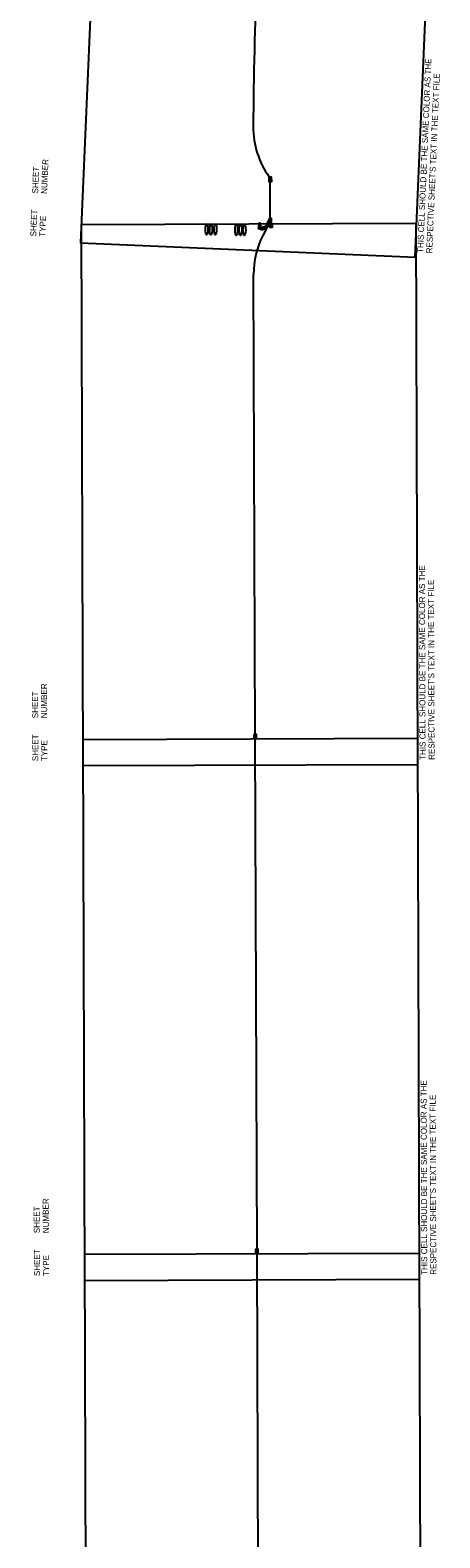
# Model space of a CAD drawing. Extents: x 601462 to 605493, y 331960 to 402715.
# Drawn here: x 602465 to 603657, y 394361 to 398753 of the extents above; entities that cross this region are included whole.
import ezdxf

# ---------------------------------------------------------------- set-up
doc = ezdxf.new("R2010")
doc.units = 0
for name, color, linetype in [('Default', 7, 'Continuous'), ('P_FTMS', 7, 'Continuous'), ('P_FTMSConduit', 7, 'Continuous'), ('P_MISC_TXT_1A (Construction)', 7, 'Continuous'), ('P_MISC_TXT_1B (Construction)', 7, 'Continuous')]:
    doc.layers.add(name, color=color, linetype=linetype)

# ---------------------------------------------------------------- blocks, each defined once
blk = doc.blocks.new('FMD')
at = {"layer": 'P_FTMS'}
for p, q in [((17, 18), (-17, 18)), ((-16, 16), (-16, 18)), ((16, 16), (-16, 16)), ((-15, 15), (-15, 20)), ((15, 19), (-15, 19)), ((15, 15), (-15, 15)), ((14, 20), (-14, 20)), ((13, 22), (-13, 22)), ((-13, 13), (-13, 21)), ((13, 13), (-13, 13)), ((-12, 12), (-12, 23)), ((12, 12), (-12, 12)), ((11, 23), (-11, 23)), ((10, 25), (-10, 25)), ((-10, 10), (-10, 24)), ((10, 10), (-10, 10)), ((-9, 9), (-9, 26)), ((9, 9), (-9, 9)), ((8, 26), (-8, 26)), ((7, 28), (-7, 28)), ((-7, 7), (-7, 27)), ((7, 7), (-7, 7)), ((-6, 6), (-6, 29)), ((6, 6), (-6, 6)), ((5, 29), (-5, 29)), ((4, 31), (-4, 31)), ((-4, 4), (-4, 30)), ((4, 4), (-4, 4)), ((-3, 3), (-3, 32)), ((3, 3), (-3, 3)), ((2, 32), (-2, 32)), ((1, 34), (-1, 34)), ((-1, 1), (-1, 33)), ((1, 1), (-1, 1)), ((0, 0), (0, 34)), ((1, 1), (1, 33)), ((3, 3), (3, 32)), ((4, 4), (4, 30)), ((6, 6), (6, 29)), ((7, 7), (7, 27)), ((9, 9), (9, 26)), ((10, 10), (10, 24)), ((12, 12), (12, 23)), ((13, 13), (13, 21)), ((15, 15), (15, 20)), ((16, 16), (16, 18))]:
    blk.add_line(p, q, dxfattribs=at)
blk.add_lwpolyline([(-17, 17), (0, 34), (17, 17), (0, 0)], close=True, dxfattribs=at)
blk = doc.blocks.new('POINT_DISPLAY')
at = {"layer": 'Default'}
blk.add_line((0, 0), (0, 0), dxfattribs=at)
blk = doc.blocks.new('_U229')
at = {"layer": 'P_FTMS'}
for p, q in [((-5, 3), (2, 0)), ((-2, 3), (-4, 0)), ((-2, 3), (-4, 0)), ((-2, 3), (-4, 1)), ((-3, 3), (-4, 1)), ((-3, 3), (-4, 1)), ((-3, 3), (-4, 2)), ((-4, 3), (-4, 2)), ((-4, 3), (-4, 3)), ((-4, 3), (2, 0)), ((-4, 3), (2, 0)), ((-4, 3), (1, 0)), ((-4, 2), (1, -1)), ((-4, 2), (1, -1)), ((-4, 2), (0, -1)), ((-4, 1), (0, -1)), ((-4, 1), (0, -1)), ((-4, 0), (0, -2)), ((1, 3), (-3, -3)), ((0, 3), (-3, -3)), ((0, 3), (-3, -2)), ((0, 3), (-3, -2)), ((-1, 3), (-3, -2)), ((-1, 3), (-3, -1)), ((-1, 3), (-3, -1)), ((-3, 3), (2, 0)), ((1, 3), (-2, -3)), ((1, 3), (-2, -3)), ((-2, 3), (3, 1)), ((2, 3), (-1, -2)), ((2, 3), (-1, -2)), ((-1, 3), (3, 1)), ((2, 3), (0, -1)), ((0, 3), (3, 1)), ((3, 3), (1, -1)), ((1, 3), (4, 1)), ((1, 3), (3, 1)), ((3, 2), (1, 0)), ((2, 3), (4, 2)), ((3, 2), (2, 0)), ((4, 2), (3, 1)), ((4, 2), (3, 1)), ((3, 2), (4, 2)), ((4, 2), (4, 2)), ((4, 2), (4, 2)), ((-4, 0), (-1, -2)), ((-3, 0), (-1, -2)), ((-3, -1), (-1, -2)), ((-3, -1), (-1, -2)), ((-3, -2), (-2, -3)), ((-3, -2), (-2, -3)), ((-3, -3), (-2, -3)), ((-3, -3), (-2, -3)), ((-3, -3), (-3, -3))]:
    blk.add_line(p, q, dxfattribs=at)
blk.add_lwpolyline([(-5, 4), (5, 2), (-3, -4)], close=True, dxfattribs=at)
blk.add_blockref('POINT_DISPLAY', (5, 2), dxfattribs=at)
blk = doc.blocks.new('_U231')
at = {"layer": 'P_FTMS'}
for p, q in [((11, 5), (-12, 4)), ((11, 4), (-12, 3)), ((12, 4), (-12, 2)), ((12, 3), (-12, 1)), ((-12, 3), (-11, -4)), ((12, 2), (-12, 1)), ((12, 2), (-12, 0)), ((12, 1), (-12, -1)), ((12, 0), (-12, -2)), ((10, 7), (-11, 6)), ((10, 7), (-11, 5)), ((11, 6), (-11, 4)), ((-11, 6), (-10, -7)), ((-11, 4), (-11, -6)), ((9, 9), (-10, 7)), ((9, 8), (-10, 7)), ((-10, 7), (-9, -8)), ((8, 9), (-9, 8)), ((-9, 9), (-7, -10)), ((-9, 8), (-8, -9)), ((7, 10), (-8, 9)), ((-8, 9), (-7, -10)), ((6, 11), (-7, 10)), ((-7, 10), (-5, -11)), ((-7, 10), (-6, -11)), ((4, 11), (-6, 11)), ((-6, 11), (-4, -11)), ((-5, 11), (-4, -12)), ((2, 12), (-4, 11)), ((-4, 12), (-2, -12)), ((-4, 11), (-3, -12)), ((-3, 12), (-1, -12)), ((-2, 12), (0, -12)), ((-2, 12), (-1, -12)), ((-1, 12), (1, -12)), ((0, 12), (2, -12)), ((1, 12), (3, -12)), ((1, 12), (2, -12)), ((2, 12), (4, -12)), ((3, 12), (4, -11)), ((4, 12), (5, -11)), ((4, 11), (6, -11)), ((5, 11), (7, -10)), ((6, 11), (7, -10)), ((7, 10), (9, -9)), ((7, 10), (8, -9)), ((8, 9), (9, -8)), ((9, 8), (10, -7)), ((10, 7), (11, -6)), ((11, 6), (11, -4)), ((11, 4), (12, -2)), ((12, -1), (-12, -2)), ((12, -1), (-12, -3)), ((12, -2), (-12, -4)), ((12, -3), (-11, -4)), ((12, -4), (-11, -5)), ((11, -4), (-11, -6)), ((11, -5), (-10, -7)), ((11, -6), (-10, -7)), ((10, -7), (-9, -8)), ((10, -7), (-9, -9)), ((9, -8), (-8, -9)), ((8, -9), (-7, -10)), ((7, -10), (-6, -11)), ((6, -11), (-5, -11)), ((4, -11), (-3, -12))]:
    blk.add_line(p, q, dxfattribs=at)
blk.add_circle((0, 0), 12.2, dxfattribs=at)
blk = doc.blocks.new('FMB')
at = {"layer": 'P_FTMS'}
for p, q in [((24, -24), (-24, 24)), ((-24, -24), (24, 24))]:
    blk.add_line(p, q, dxfattribs=at)
blk.add_lwpolyline([(24, -24), (24, 24), (-24, 24), (-24, -24)], close=True, dxfattribs=at)
blk = doc.blocks.new('FTMS_FCV')
at = {"layer": 'P_FTMS'}
blk.add_line((13, 16), (1, -22), dxfattribs=at)
blk.add_lwpolyline([(39, 24), (-39, 24), (-39, -24), (39, -24)], close=True, dxfattribs=at)
blk.add_lwpolyline([(-12, 16), (1, -22)], dxfattribs=at)

msp = doc.modelspace()

# ---------------------------------------------------------------- linework, layer by layer
at = {"layer": 'P_FTMS'}
msp.add_circle((603146.8, 398177.3), 3.75, dxfattribs=at)
for centre, start, end in [((603146.5, 398172.8), 32.6299, 138.8855), ((603147.1, 398181.7), 212.6299, 318.8855)]:
    msp.add_arc(centre, 3.75, start, end, dxfattribs=at)
for centre in [(602978.5, 398172.8), (602991, 398172.6), (603003.8, 398172.4), (603064.9, 398171), (603076.9, 398170.7), (603088.3, 398170.5)]:
    msp.add_ellipse(centre, major_axis=(0.3, 16), ratio=0.23471, dxfattribs=at)
at = {"layer": 'P_FTMSConduit'}
for p, q in [((603163.5, 398203.7), (603163.4, 398312)), ((603149.3, 398180.1), (603159.6, 398198)), ((603144, 398179.7), (603140.5, 398179.4)), ((603160.8, 398190.9), (603142, 398154.4)), ((603162, 398182.7), (603150.5, 398177.1)), ((603119.8, 396701.5), (603115, 398040.6)), ((603125.1, 395202), (603119.8, 396688.7)), ((603130.5, 393701.2), (603125.2, 395189.2))]:
    msp.add_line(p, q, dxfattribs=at)
msp.add_lwpolyline([(603137.8, 398171.8), (603134.6, 398172.4)], dxfattribs=at)
for centre, radius, start, end in [((614541.5, 398405.4), 11427.7, 175.21781, 179.66703), ((603364, 398470.4), 250, 179.667, 215.616), ((603365, 398041.5), 250, 153.1452, 180.2043), ((603137.5, 398189.1), 17.3, 270.9886, 297.4021)]:
    msp.add_arc(centre, radius, start, end, dxfattribs=at)
at = {"layer": 'P_MISC_TXT_1A (Construction)'}
for points in [[(603593.2, 396614.2), (603588, 398189.2), (602613, 398185.9), (602618.2, 396610.9)], [(603593.2, 396614.2), (603588, 398189.2), (602613, 398185.9), (602618.2, 396610.9)], [(603603.1, 393614.2), (603597.9, 395189.2), (602622.9, 395186), (602628.1, 393611)], [(603603.1, 393614.2), (603597.9, 395189.2), (602622.9, 395186), (602628.1, 393611)]]:
    msp.add_lwpolyline(points, close=True, dxfattribs=at)
at = {"layer": 'P_MISC_TXT_1B (Construction)'}
for points in [[(603585.5, 398091.6), (603652.9, 399665.1), (602678.8, 399706.9), (602611.4, 398133.3)], [(603585.5, 398091.6), (603652.9, 399665.1), (602678.8, 399706.9), (602611.4, 398133.3)], [(603598.2, 395114.2), (603593, 396689.2), (602618, 396685.9), (602623.2, 395111)], [(603598.2, 395114.2), (603593, 396689.2), (602618, 396685.9), (602623.2, 395111)]]:
    msp.add_lwpolyline(points, close=True, dxfattribs=at)

# ---------------------------------------------------------------- block references
at = {"layer": 'P_FTMS'}
for name, p, xscale, yscale, rotation in [('FTMS_FCV', (603163.7, 398318.4), 0.16404166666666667, 0.1640416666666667, 90.75145918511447), ('FTMS_FCV', (603163.6, 398197.3), 0.16404166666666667, 0.1640416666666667, 90.75145918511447), ('_U231', (603133.4, 398176.7), 0.32808333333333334, 0.32808333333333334, 2.5604819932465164), ('FMD', (603130.2, 398183.6), 0.16404166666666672, 0.16404166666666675, -91.54665377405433), ('FMD', (603130.3, 398189.2), 0.16404166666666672, 0.16404166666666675, -91.54665377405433), ('_U229', (603139.8, 398176.4), 0.19685000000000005, 0.19685000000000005, 109.6160567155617), ('FMB', (603165.9, 398182.7), 0.16404166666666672, 0.16404166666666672, 89.4786762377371), ('FTMS_FCV', (603119.5, 396695.1), 0.16404166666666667, 0.1640416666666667, 90.75145918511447), ('FTMS_FCV', (603124.7, 395195.6), 0.16404166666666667, 0.1640416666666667, 90.75145918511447)]:
    msp.add_blockref(name, p, dxfattribs=dict(at, xscale=xscale, yscale=yscale, rotation=rotation))

# ---------------------------------------------------------------- texts
at = {"layer": 'P_MISC_TXT_1A (Construction)'}
for s, p in [('THIS CELL SHOULD BE THE SAME COLOR AS THE', (603615.8, 396627.2)), ('THIS CELL SHOULD BE THE SAME COLOR AS THE', (603615.8, 396627.2)), ("RESPECTIVE SHEET'S TEXT IN THE TEXT FILE", (603642, 396627.3)), ("RESPECTIVE SHEET'S TEXT IN THE TEXT FILE", (603642, 396627.3)), ('NUMBER', (602514.1, 396748.6)), ('NUMBER', (602514.1, 396748.6)), ('SHEET', (602487.9, 396748.5)), ('SHEET', (602487.9, 396748.5)), ('SHEET', (602488.3, 396623.5)), ('SHEET', (602488.3, 396623.5)), ('TYPE', (602514.5, 396623.6)), ('TYPE', (602514.5, 396623.6))]:
    msp.add_text(s, height=17.5, rotation=90.1893, dxfattribs=at).set_placement(p)
at = {"layer": 'P_MISC_TXT_1B (Construction)'}
for s, rotation, p in [('THIS CELL SHOULD BE THE SAME COLOR AS THE', 87.5465, (603608.6, 398103.5)), ('THIS CELL SHOULD BE THE SAME COLOR AS THE', 87.5465, (603608.6, 398103.5)), ("RESPECTIVE SHEET'S TEXT IN THE TEXT FILE", 87.5465, (603634.9, 398102.4)), ("RESPECTIVE SHEET'S TEXT IN THE TEXT FILE", 87.5465, (603634.9, 398102.4)), ('NUMBER', 87.5465, (602513.7, 398275.6)), ('NUMBER', 87.5465, (602513.7, 398275.6)), ('SHEET', 87.5465, (602487.5, 398276.7)), ('SHEET', 87.5465, (602487.5, 398276.7)), ('SHEET', 87.5465, (602482.2, 398151.8)), ('SHEET', 87.5465, (602482.2, 398151.8)), ('TYPE', 87.5465, (602508.4, 398150.7)), ('TYPE', 87.5465, (602508.4, 398150.7)), ('THIS CELL SHOULD BE THE SAME COLOR AS THE', 90.1893, (603620.7, 395127.2)), ('THIS CELL SHOULD BE THE SAME COLOR AS THE', 90.1893, (603620.7, 395127.2)), ("RESPECTIVE SHEET'S TEXT IN THE TEXT FILE", 90.1893, (603647, 395127.3)), ("RESPECTIVE SHEET'S TEXT IN THE TEXT FILE", 90.1893, (603647, 395127.3)), ('NUMBER', 90.1893, (602519.1, 395248.6)), ('NUMBER', 90.1893, (602519.1, 395248.6)), ('SHEET', 90.1893, (602492.8, 395248.5)), ('SHEET', 90.1893, (602492.8, 395248.5)), ('SHEET', 90.1893, (602493.3, 395123.5)), ('SHEET', 90.1893, (602493.3, 395123.5)), ('TYPE', 90.1893, (602519.5, 395123.6)), ('TYPE', 90.1893, (602519.5, 395123.6))]:
    msp.add_text(s, height=17.5, rotation=rotation, dxfattribs=at).set_placement(p)

doc.saveas('drawing.dxf')
